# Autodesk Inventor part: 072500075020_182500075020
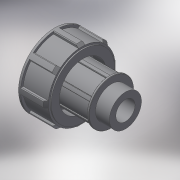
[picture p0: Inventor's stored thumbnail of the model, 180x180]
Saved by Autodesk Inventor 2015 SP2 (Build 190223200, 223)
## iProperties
Created: 2017-04
Part Number: 072500075020_182500075020
Material: Generic
Description: PLASSON THREADED ADAPTOR 75-2"
Document SubType Name: Modeling
Designer: KIM
Density: 1 g/cm^3
Appearance: Default
Author: KIM
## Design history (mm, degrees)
derived "07250.ipt"
feature "Solid1::07250.ipt"
tag "TaggingFeature1"
body "Solid1"
other parameters: "d1" = 59.614, "d2" = 132, "d3" = 26, "d6" = 132, "d7" = 122.76, "d8" = 105.6, "d9" = 75, "d10" = 83.4596, "d12" = 35.7684, "d13" = 47.6912, "d14" = 29.9, "d15" = 99, "d16" = 3.96, "d17" = 52.8, "d18" = 26, "d19" = 31.2, "d24" = 11.9228, "d25" = 5.9614, "d27" = 0, "d28" = 4.76912, "d31" = 1.19228, "d35" = 360 deg, "d41" = 29.337, "d56" = 78.75, "d57" = 7.5, "d58" = 3.75, "d60" = 0, "d61" = 0.59614, "d64" = 0.59614, "d68" = 360 deg, "d_" = 75, "R_" = 59.614, "E_" = 132, "H_" = 132, "l_2" = 26, "d55" = 75
